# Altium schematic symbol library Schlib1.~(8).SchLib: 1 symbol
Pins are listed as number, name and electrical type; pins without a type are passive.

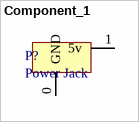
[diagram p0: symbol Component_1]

## Component_1
designator P?, comment Power Jack
footprint PCBComponent_1
pins: 0 GND (power), 1 5v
